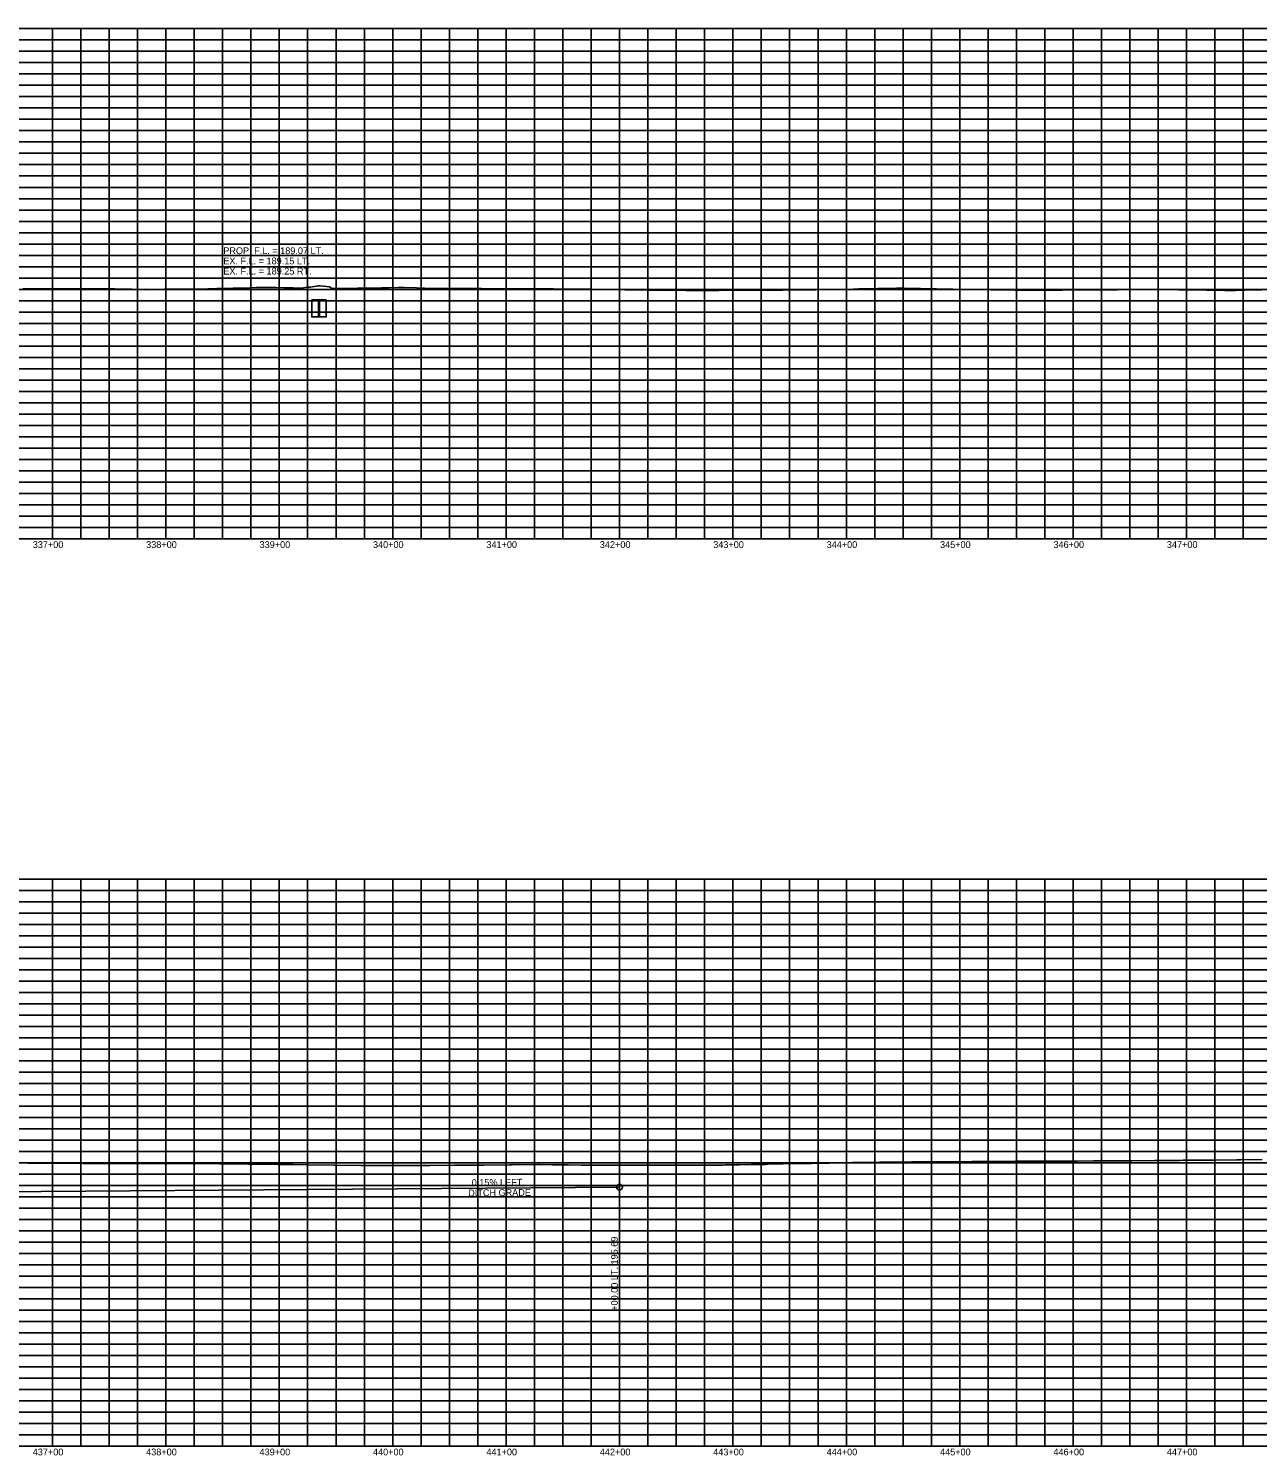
# Model space of a CAD drawing. Extents: x 1399671 to 1408349, y 1930471 to 1933387.
# Drawn here: x 1404003 to 1405087, y 1930471 to 1931729 of the extents above; entities that cross this region are included whole.
import ezdxf

# ---------------------------------------------------------------- set-up
doc = ezdxf.new("R2010")
doc.units = 0
for name, color, linetype in [('R_Drainage', 7, 'Continuous'), ('R_Exist Surface', 7, 'Continuous'), ('R_Grid', 7, 'Continuous'), ('R_Grid Annot', 7, 'Continuous'), ('R_Vert Alg', 7, 'Continuous'), ('R_Vert Alg Annot', 7, 'Continuous')]:
    doc.layers.add(name, color=color, linetype=linetype)

msp = doc.modelspace()

# ---------------------------------------------------------------- linework, layer by layer
at = {"layer": 'R_Drainage'}
for p, q in [((1404258.8, 1931489.4), (1404252.8, 1931489.4)), ((1404258.8, 1931474.4), (1404258.8, 1931489.4)), ((1404258.8, 1931489.4), (1404258.8, 1931474.4)), ((1404259.6, 1931489.4), (1404258.8, 1931489.4)), ((1404259.6, 1931474.4), (1404259.6, 1931489.4)), ((1404258.8, 1931474.4), (1404259.2, 1931474.4)), ((1404259.2, 1931474.4), (1404259.6, 1931474.4))]:
    msp.add_line(p, q, dxfattribs=at)
for points in [[(1404252.8, 1931489.4), (1404252.8, 1931474.4), (1404258.8, 1931474.4)], [(1404259.6, 1931474.4), (1404265.6, 1931474.4), (1404265.6, 1931489.4), (1404259.6, 1931489.4), (1404259.6, 1931474.4)]]:
    msp.add_lwpolyline(points, dxfattribs=at)
at = {"layer": 'R_Exist Surface'}
for points in [[(1403998.1, 1931499.2), (1404006.3, 1931499.2), (1404014.3, 1931499.2), (1404022.2, 1931499.2), (1404029.4, 1931499.2), (1404035.8, 1931499.2), (1404045.2, 1931499.2), (1404051.6, 1931499.1), (1404061.9, 1931499.1), (1404067.6, 1931499), (1404079.3, 1931499), (1404083.9, 1931498.9), (1404094.2, 1931498.8), (1404100, 1931498.6), (1404106.2, 1931498.7), (1404115.8, 1931498.6), (1404122.6, 1931498.8), (1404131.5, 1931498.7), (1404138.7, 1931498.8), (1404147, 1931498.8), (1404154.6, 1931498.9), (1404161.2, 1931499.1), (1404169.1, 1931499.3), (1404175.4, 1931499.5), (1404183.6, 1931499.6), (1404189.6, 1931499.8), (1404198.1, 1931500), (1404203.8, 1931500.2), (1404212.5, 1931500.3), (1404221, 1931500.2), (1404228.1, 1931500), (1404236.3, 1931499.9), (1404243.8, 1931499.6), (1404249.2, 1931500.6), (1404251.3, 1931500.6), (1404258.7, 1931501.9), (1404260.3, 1931501.9), (1404268.5, 1931500.9), (1404270.4, 1931499.3), (1404279.1, 1931499.3), (1404285, 1931499.5), (1404293.2, 1931499.6), (1404299.7, 1931499.7), (1404307.2, 1931499.8), (1404314.3, 1931500), (1404321.1, 1931500), (1404329.1, 1931500.3), (1404334.4, 1931500.2), (1404345.2, 1931499.9), (1404352.3, 1931499.8), (1404360.4, 1931499.5), (1404368.8, 1931499.4), (1404377.1, 1931499.3), (1404384.9, 1931499.3), (1404393.6, 1931499.3), (1404402.6, 1931499.3), (1404410.4, 1931499.2), (1404420.9, 1931499.2), (1404427.5, 1931499.2), (1404440, 1931499.2), (1404445.2, 1931499.2), (1404449.9, 1931499.2), (1404461.6, 1931499), (1404465.9, 1931499), (1404478.1, 1931498.9), (1404482.1, 1931498.9), (1404494.8, 1931498.7), (1404498.4, 1931498.7), (1404511.7, 1931498.5), (1404514.9, 1931498.5), (1404528.9, 1931498.3), (1404531.6, 1931498.3), (1404534.2, 1931498.3), (1404548.5, 1931498), (1404550.6, 1931498), (1404565.6, 1931497.7), (1404567.1, 1931497.8), (1404583, 1931497.5), (1404583.8, 1931497.5), (1404596.8, 1931497.6), (1404597.8, 1931497.6), (1404610.6, 1931497.7), (1404611.7, 1931497.7), (1404624.4, 1931497.8), (1404625.7, 1931497.7), (1404638.3, 1931497.8), (1404639.7, 1931497.8), (1404652.2, 1931497.9), (1404653.7, 1931497.9), (1404666.2, 1931498), (1404667.8, 1931498), (1404680.1, 1931498.1), (1404681.7, 1931498), (1404693.9, 1931498.1), (1404695.6, 1931498.1), (1404697.2, 1931498.1), (1404713.4, 1931498.6), (1404716.8, 1931498.6), (1404730.1, 1931498.9), (1404735, 1931499), (1404746.1, 1931499.2), (1404752, 1931499.3), (1404758.1, 1931499.3), (1404768.3, 1931499.6), (1404775.3, 1931499.6), (1404783, 1931499.4), (1404789.5, 1931499.4), (1404797.6, 1931499.2), (1404803.8, 1931499.1), (1404812.4, 1931498.9), (1404818.2, 1931498.9), (1404827.3, 1931498.6), (1404832.7, 1931498.6), (1404838.2, 1931498.5), (1404846, 1931498.4), (1404851.5, 1931498.3), (1404859.4, 1931498.2), (1404864.8, 1931498.1), (1404872.8, 1931498), (1404878.1, 1931497.9), (1404886.1, 1931497.8), (1404892, 1931497.8), (1404900.3, 1931497.9), (1404906.8, 1931497.9), (1404914.5, 1931498), (1404921.3, 1931498.1), (1404928.8, 1931498.1), (1404935.1, 1931498.2), (1404943.1, 1931498.2), (1404949, 1931498.2), (1404957.6, 1931498.3), (1404963.2, 1931498.3), (1404972.1, 1931498.4), (1404977.5, 1931498.4), (1404986.6, 1931498.5), (1404991.8, 1931498.5), (1405001.1, 1931498.6), (1405008.8, 1931498.6), (1405017.2, 1931498.3), (1405025.8, 1931498.1), (1405033.6, 1931498.1), (1405041.8, 1931497.9), (1405050.3, 1931497.9), (1405058, 1931497.7), (1405067.4, 1931497.7), (1405075.4, 1931498), (1405083.2, 1931498.2), (1405090.4, 1931498.1)], [(1404002.2, 1930728.3), (1404025.6, 1930728.2), (1404026.5, 1930728.2), (1404027.4, 1930728.2), (1404050.9, 1930728), (1404051.4, 1930728), (1404075.2, 1930728), (1404075.7, 1930728), (1404076.2, 1930728), (1404100.1, 1930727.9), (1404100.5, 1930727.9), (1404122.8, 1930727.9), (1404123.9, 1930727.9), (1404146, 1930727.9), (1404147.2, 1930727.9), (1404147.9, 1930727.9), (1404159.8, 1930727.8), (1404171.9, 1930727.6), (1404172.4, 1930727.6), (1404184.5, 1930727.5), (1404185, 1930727.5), (1404197.2, 1930727.4), (1404197.7, 1930727.4), (1404209.9, 1930727.3), (1404210.8, 1930727.3), (1404223, 1930727.2), (1404235.3, 1930727), (1404236.1, 1930727), (1404248.3, 1930726.9), (1404249.1, 1930726.9), (1404272.2, 1930726.6), (1404272.9, 1930726.6), (1404296, 1930726.3), (1404296.4, 1930726.3), (1404311.3, 1930726.3), (1404325.8, 1930726.3), (1404326.6, 1930726.3), (1404341, 1930726.3), (1404342, 1930726.3), (1404356.1, 1930726.3), (1404357.3, 1930726.3), (1404378.8, 1930726.4), (1404380.5, 1930726.4), (1404402, 1930726.4), (1404403.7, 1930726.5), (1404404.7, 1930726.5), (1404427.6, 1930726.7), (1404428.5, 1930726.7), (1404429.5, 1930726.7), (1404452.4, 1930727), (1404453.3, 1930727), (1404465.1, 1930726.9), (1404467.2, 1930726.8), (1404478.9, 1930726.7), (1404490.5, 1930726.6), (1404492.9, 1930726.5), (1404504.5, 1930726.4), (1404505.8, 1930726.4), (1404517.3, 1930726.4), (1404518.6, 1930726.4), (1404530, 1930726.4), (1404541.5, 1930726.4), (1404542.8, 1930726.5), (1404554.2, 1930726.5), (1404555.5, 1930726.5), (1404577.1, 1930726.5), (1404580, 1930726.5), (1404601, 1930726.5), (1404604.4, 1930726.5), (1404615.2, 1930726.6), (1404617.1, 1930726.7), (1404627.8, 1930726.8), (1404629.7, 1930726.9), (1404640.4, 1930727), (1404642.3, 1930727.1), (1404652.9, 1930727.2), (1404654.9, 1930727.3), (1404666.3, 1930727.5), (1404668.4, 1930727.5), (1404679.7, 1930727.8), (1404681.9, 1930727.8), (1404693.2, 1930728), (1404695.4, 1930728.1), (1404706.6, 1930728.3), (1404708.9, 1930728.3), (1404729.2, 1930728.7), (1404733.4, 1930728.8), (1404753.8, 1930729.1), (1404758, 1930729.2), (1404768.6, 1930729.2), (1404770.8, 1930729.2), (1404781.5, 1930729.3), (1404783.6, 1930729.3), (1404794.3, 1930729.3), (1404796.4, 1930729.3), (1404807.2, 1930729.4), (1404809.2, 1930729.4), (1404819.9, 1930729.4), (1404822, 1930729.5), (1404832.6, 1930729.5), (1404834.7, 1930729.6), (1404845.3, 1930729.6), (1404847.4, 1930729.7), (1404858, 1930729.7), (1404860.1, 1930729.8), (1404871, 1930729.8), (1404873.1, 1930729.9), (1404884.1, 1930729.9), (1404886.1, 1930729.9), (1404888.1, 1930730), (1404899.1, 1930730), (1404901, 1930730), (1404912.1, 1930730.1), (1404914.3, 1930730.1), (1404928.1, 1930730.1), (1404942.2, 1930730.2), (1404944.1, 1930730.2), (1404958.4, 1930730.2), (1404960.1, 1930730.2), (1404974.6, 1930730.2), (1404976, 1930730.2), (1404996, 1930730.5), (1404998.7, 1930730.5), (1405018.1, 1930730.7), (1405021.3, 1930730.8), (1405024.4, 1930730.8), (1405044.9, 1930731), (1405047.9, 1930731), (1405068.4, 1930731.2), (1405071.7, 1930731.2), (1405090.8, 1930731.5)]]:
    msp.add_lwpolyline(points, dxfattribs=at)
at = {"layer": 'R_Grid'}
for p, q in [((1400324.2, 1931728.6), (1408324.2, 1931728.6)), ((1400324.2, 1931728.6), (1408324.2, 1931728.6)), ((1404024.2, 1931278.6), (1404024.2, 1931728.6)), ((1404049.2, 1931278.6), (1404049.2, 1931728.6)), ((1404074.2, 1931278.6), (1404074.2, 1931728.6)), ((1404099.2, 1931278.6), (1404099.2, 1931728.6)), ((1404124.2, 1931278.6), (1404124.2, 1931728.6)), ((1404149.2, 1931278.6), (1404149.2, 1931728.6)), ((1404174.2, 1931278.6), (1404174.2, 1931728.6)), ((1404199.2, 1931278.6), (1404199.2, 1931728.6)), ((1404224.2, 1931278.6), (1404224.2, 1931728.6)), ((1404249.2, 1931278.6), (1404249.2, 1931728.6)), ((1404274.2, 1931278.6), (1404274.2, 1931728.6)), ((1404299.2, 1931278.6), (1404299.2, 1931728.6)), ((1404324.2, 1931278.6), (1404324.2, 1931728.6)), ((1404349.2, 1931278.6), (1404349.2, 1931728.6)), ((1404374.2, 1931278.6), (1404374.2, 1931728.6)), ((1404399.2, 1931278.6), (1404399.2, 1931728.6)), ((1404424.2, 1931278.6), (1404424.2, 1931728.6)), ((1404449.2, 1931278.6), (1404449.2, 1931728.6)), ((1404474.2, 1931278.6), (1404474.2, 1931728.6)), ((1404499.2, 1931278.6), (1404499.2, 1931728.6)), ((1404524.2, 1931278.6), (1404524.2, 1931728.6)), ((1404549.2, 1931278.6), (1404549.2, 1931728.6)), ((1404574.2, 1931278.6), (1404574.2, 1931728.6)), ((1404599.2, 1931278.6), (1404599.2, 1931728.6)), ((1404624.2, 1931278.6), (1404624.2, 1931728.6)), ((1404649.2, 1931278.6), (1404649.2, 1931728.6)), ((1404674.2, 1931278.6), (1404674.2, 1931728.6)), ((1404699.2, 1931278.6), (1404699.2, 1931728.6)), ((1404724.2, 1931278.6), (1404724.2, 1931728.6)), ((1404749.2, 1931278.6), (1404749.2, 1931728.6)), ((1404774.2, 1931278.6), (1404774.2, 1931728.6)), ((1404799.2, 1931278.6), (1404799.2, 1931728.6)), ((1404824.2, 1931278.6), (1404824.2, 1931728.6)), ((1404849.2, 1931278.6), (1404849.2, 1931728.6)), ((1404874.2, 1931278.6), (1404874.2, 1931728.6)), ((1404899.2, 1931278.6), (1404899.2, 1931728.6)), ((1404924.2, 1931278.6), (1404924.2, 1931728.6)), ((1404949.2, 1931278.6), (1404949.2, 1931728.6)), ((1404974.2, 1931278.6), (1404974.2, 1931728.6)), ((1404999.2, 1931278.6), (1404999.2, 1931728.6)), ((1405024.2, 1931278.6), (1405024.2, 1931728.6)), ((1405049.2, 1931278.6), (1405049.2, 1931728.6)), ((1405074.2, 1931278.6), (1405074.2, 1931728.6)), ((1400324.2, 1931718.6), (1408324.2, 1931718.6)), ((1400324.2, 1931708.6), (1408324.2, 1931708.6)), ((1400324.2, 1931698.6), (1408324.2, 1931698.6)), ((1400324.2, 1931688.6), (1408324.2, 1931688.6)), ((1400324.2, 1931678.6), (1408324.2, 1931678.6)), ((1400324.2, 1931668.6), (1408324.2, 1931668.6)), ((1400324.2, 1931658.6), (1408324.2, 1931658.6)), ((1400324.2, 1931648.6), (1408324.2, 1931648.6)), ((1400324.2, 1931638.6), (1408324.2, 1931638.6)), ((1400324.2, 1931628.6), (1408324.2, 1931628.6)), ((1400324.2, 1931618.6), (1408324.2, 1931618.6)), ((1400324.2, 1931608.6), (1408324.2, 1931608.6)), ((1400324.2, 1931598.6), (1408324.2, 1931598.6)), ((1400324.2, 1931588.6), (1408324.2, 1931588.6)), ((1400324.2, 1931578.6), (1408324.2, 1931578.6)), ((1400324.2, 1931568.6), (1408324.2, 1931568.6)), ((1400324.2, 1931558.6), (1408324.2, 1931558.6)), ((1400324.2, 1931548.6), (1408324.2, 1931548.6)), ((1400324.2, 1931538.6), (1408324.2, 1931538.6)), ((1400324.2, 1931528.6), (1408324.2, 1931528.6)), ((1400324.2, 1931518.6), (1408324.2, 1931518.6)), ((1400324.2, 1931508.6), (1408324.2, 1931508.6)), ((1400324.2, 1931498.6), (1408324.2, 1931498.6)), ((1400324.2, 1931488.6), (1408324.2, 1931488.6)), ((1400324.2, 1931478.6), (1408324.2, 1931478.6)), ((1400324.2, 1931468.6), (1408324.2, 1931468.6)), ((1400324.2, 1931458.6), (1408324.2, 1931458.6)), ((1400324.2, 1931448.6), (1408324.2, 1931448.6)), ((1400324.2, 1931438.6), (1408324.2, 1931438.6)), ((1400324.2, 1931428.6), (1408324.2, 1931428.6)), ((1400324.2, 1931418.6), (1408324.2, 1931418.6)), ((1400324.2, 1931408.6), (1408324.2, 1931408.6)), ((1400324.2, 1931398.6), (1408324.2, 1931398.6)), ((1400324.2, 1931388.6), (1408324.2, 1931388.6)), ((1400324.2, 1931378.6), (1408324.2, 1931378.6)), ((1400324.2, 1931368.6), (1408324.2, 1931368.6)), ((1400324.2, 1931358.6), (1408324.2, 1931358.6)), ((1400324.2, 1931348.6), (1408324.2, 1931348.6)), ((1400324.2, 1931338.6), (1408324.2, 1931338.6)), ((1400324.2, 1931328.6), (1408324.2, 1931328.6)), ((1400324.2, 1931318.6), (1408324.2, 1931318.6)), ((1400324.2, 1931308.6), (1408324.2, 1931308.6)), ((1400324.2, 1931298.6), (1408324.2, 1931298.6)), ((1400324.2, 1931288.6), (1408324.2, 1931288.6)), ((1400324.2, 1931278.6), (1408324.2, 1931278.6)), ((1400324.2, 1930978.6), (1407124.2, 1930978.6)), ((1400324.2, 1930978.6), (1407124.2, 1930978.6)), ((1404024.2, 1930478.6), (1404024.2, 1930978.6)), ((1404049.2, 1930478.6), (1404049.2, 1930978.6)), ((1404074.2, 1930478.6), (1404074.2, 1930978.6)), ((1404099.2, 1930478.6), (1404099.2, 1930978.6)), ((1404124.2, 1930478.6), (1404124.2, 1930978.6)), ((1404149.2, 1930478.6), (1404149.2, 1930978.6)), ((1404174.2, 1930478.6), (1404174.2, 1930978.6)), ((1404199.2, 1930478.6), (1404199.2, 1930978.6)), ((1404224.2, 1930478.6), (1404224.2, 1930978.6)), ((1404249.2, 1930478.6), (1404249.2, 1930978.6)), ((1404274.2, 1930478.6), (1404274.2, 1930978.6)), ((1404299.2, 1930478.6), (1404299.2, 1930978.6)), ((1404324.2, 1930478.6), (1404324.2, 1930978.6)), ((1404349.2, 1930478.6), (1404349.2, 1930978.6)), ((1404374.2, 1930478.6), (1404374.2, 1930978.6)), ((1404399.2, 1930478.6), (1404399.2, 1930978.6)), ((1404424.2, 1930478.6), (1404424.2, 1930978.6)), ((1404449.2, 1930478.6), (1404449.2, 1930978.6)), ((1404474.2, 1930478.6), (1404474.2, 1930978.6)), ((1404499.2, 1930478.6), (1404499.2, 1930978.6)), ((1404524.2, 1930478.6), (1404524.2, 1930978.6)), ((1404549.2, 1930478.6), (1404549.2, 1930978.6)), ((1404574.2, 1930478.6), (1404574.2, 1930978.6)), ((1404599.2, 1930478.6), (1404599.2, 1930978.6)), ((1404624.2, 1930478.6), (1404624.2, 1930978.6)), ((1404649.2, 1930478.6), (1404649.2, 1930978.6)), ((1404674.2, 1930478.6), (1404674.2, 1930978.6)), ((1404699.2, 1930478.6), (1404699.2, 1930978.6)), ((1404724.2, 1930478.6), (1404724.2, 1930978.6)), ((1404749.2, 1930478.6), (1404749.2, 1930978.6)), ((1404774.2, 1930478.6), (1404774.2, 1930978.6)), ((1404799.2, 1930478.6), (1404799.2, 1930978.6)), ((1404824.2, 1930478.6), (1404824.2, 1930978.6)), ((1404849.2, 1930478.6), (1404849.2, 1930978.6)), ((1404874.2, 1930478.6), (1404874.2, 1930978.6)), ((1404899.2, 1930478.6), (1404899.2, 1930978.6)), ((1404924.2, 1930478.6), (1404924.2, 1930978.6)), ((1404949.2, 1930478.6), (1404949.2, 1930978.6)), ((1404974.2, 1930478.6), (1404974.2, 1930978.6)), ((1404999.2, 1930478.6), (1404999.2, 1930978.6)), ((1405024.2, 1930478.6), (1405024.2, 1930978.6)), ((1405049.2, 1930478.6), (1405049.2, 1930978.6)), ((1405074.2, 1930478.6), (1405074.2, 1930978.6)), ((1400324.2, 1930968.6), (1407124.2, 1930968.6)), ((1400324.2, 1930958.6), (1407124.2, 1930958.6)), ((1400324.2, 1930948.6), (1407124.2, 1930948.6)), ((1400324.2, 1930938.6), (1407124.2, 1930938.6)), ((1400324.2, 1930928.6), (1407124.2, 1930928.6)), ((1400324.2, 1930918.6), (1407124.2, 1930918.6)), ((1400324.2, 1930908.6), (1407124.2, 1930908.6)), ((1400324.2, 1930898.6), (1407124.2, 1930898.6)), ((1400324.2, 1930888.6), (1407124.2, 1930888.6)), ((1400324.2, 1930878.6), (1407124.2, 1930878.6)), ((1400324.2, 1930868.6), (1407124.2, 1930868.6)), ((1400324.2, 1930858.6), (1407124.2, 1930858.6)), ((1400324.2, 1930848.6), (1407124.2, 1930848.6)), ((1400324.2, 1930838.6), (1407124.2, 1930838.6)), ((1400324.2, 1930828.6), (1407124.2, 1930828.6)), ((1400324.2, 1930818.6), (1407124.2, 1930818.6)), ((1400324.2, 1930808.6), (1407124.2, 1930808.6)), ((1400324.2, 1930798.6), (1407124.2, 1930798.6)), ((1400324.2, 1930788.6), (1407124.2, 1930788.6)), ((1400324.2, 1930778.6), (1407124.2, 1930778.6)), ((1400324.2, 1930768.6), (1407124.2, 1930768.6)), ((1400324.2, 1930758.6), (1407124.2, 1930758.6)), ((1400324.2, 1930748.6), (1407124.2, 1930748.6)), ((1400324.2, 1930738.6), (1407124.2, 1930738.6)), ((1400324.2, 1930728.6), (1407124.2, 1930728.6)), ((1400324.2, 1930718.6), (1407124.2, 1930718.6)), ((1400324.2, 1930708.6), (1407124.2, 1930708.6)), ((1400324.2, 1930698.6), (1407124.2, 1930698.6)), ((1400324.2, 1930688.6), (1407124.2, 1930688.6)), ((1400324.2, 1930678.6), (1407124.2, 1930678.6)), ((1400324.2, 1930668.6), (1407124.2, 1930668.6)), ((1400324.2, 1930658.6), (1407124.2, 1930658.6)), ((1400324.2, 1930648.6), (1407124.2, 1930648.6)), ((1400324.2, 1930638.6), (1407124.2, 1930638.6)), ((1400324.2, 1930628.6), (1407124.2, 1930628.6)), ((1400324.2, 1930618.6), (1407124.2, 1930618.6)), ((1400324.2, 1930608.6), (1407124.2, 1930608.6)), ((1400324.2, 1930598.6), (1407124.2, 1930598.6)), ((1400324.2, 1930588.6), (1407124.2, 1930588.6)), ((1400324.2, 1930578.6), (1407124.2, 1930578.6)), ((1400324.2, 1930568.6), (1407124.2, 1930568.6)), ((1400324.2, 1930558.6), (1407124.2, 1930558.6)), ((1400324.2, 1930548.6), (1407124.2, 1930548.6)), ((1400324.2, 1930538.6), (1407124.2, 1930538.6)), ((1400324.2, 1930528.6), (1407124.2, 1930528.6)), ((1400324.2, 1930518.6), (1407124.2, 1930518.6)), ((1400324.2, 1930508.6), (1407124.2, 1930508.6)), ((1400324.2, 1930498.6), (1407124.2, 1930498.6)), ((1400324.2, 1930488.6), (1407124.2, 1930488.6)), ((1400324.2, 1930478.6), (1407124.2, 1930478.6))]:
    msp.add_line(p, q, dxfattribs=at)
at = {"layer": 'R_Vert Alg'}
msp.add_line((1402758.2, 1930693.8), (1404524.2, 1930707.1), dxfattribs=at)
at = {"layer": 'R_Vert Alg Annot'}
for p, q in [((1404524.2, 1930707.1), (1404524.2, 1930682.1)), ((1404524.2, 1930682.1), (1404524.2, 1930598.1))]:
    msp.add_line(p, q, dxfattribs=at)
msp.add_circle((1404524.2, 1930707.1), 2.5, dxfattribs=at)

# ---------------------------------------------------------------- texts
at = {"layer": 'R_Grid Annot'}
for s, p in [('337+00', (1404006.8, 1931270.6)), ('338+00', (1404106.8, 1931270.6)), ('339+00', (1404206.8, 1931270.6)), ('340+00', (1404306.8, 1931270.6)), ('341+00', (1404406.8, 1931270.6)), ('342+00', (1404506.8, 1931270.6)), ('343+00', (1404606.8, 1931270.6)), ('344+00', (1404706.8, 1931270.6)), ('345+00', (1404806.8, 1931270.6)), ('346+00', (1404906.8, 1931270.6)), ('347+00', (1405006.8, 1931270.6)), ('437+00', (1404006.8, 1930470.6)), ('438+00', (1404106.8, 1930470.6)), ('439+00', (1404206.8, 1930470.6)), ('440+00', (1404306.8, 1930470.6)), ('441+00', (1404406.8, 1930470.6)), ('442+00', (1404506.8, 1930470.6)), ('443+00', (1404606.8, 1930470.6)), ('444+00', (1404706.8, 1930470.6)), ('445+00', (1404806.8, 1930470.6)), ('446+00', (1404906.8, 1930470.6)), ('447+00', (1405006.8, 1930470.6))]:
    msp.add_text(s, height=6, dxfattribs=at).set_placement(p)
at = {"layer": 'R_Vert Alg Annot'}
for s, p in [('PROP. F.L. = 189.07 LT.', (1404174.8, 1931529.7)), ('EX. F.L. = 189.15 LT.', (1404174.8, 1931520.7)), ('EX. F.L. = 189.25 RT.', (1404174.8, 1931511.7))]:
    msp.add_text(s, height=6, dxfattribs=at).set_placement(p)
for s, rotation, p in [('0.15% LEFT', 0.4299, (1404393.9, 1930708.1)), ('DITCH GRADE', 0.4299, (1404390.8, 1930699)), ('+00.00 LT. 195.69', 90, (1404522.7, 1930598.1))]:
    msp.add_text(s, height=6, rotation=rotation, dxfattribs=at).set_placement(p)

doc.saveas('drawing.dxf')
